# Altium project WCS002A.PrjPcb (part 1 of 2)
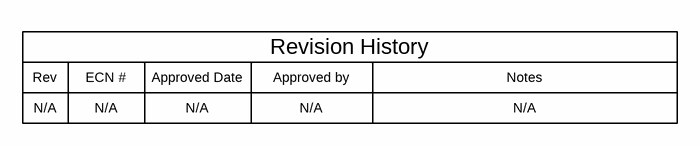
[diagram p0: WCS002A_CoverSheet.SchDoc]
CopyrightYear: 2015; PCB_Layout: Tessolve; PCB_Rev: A; PRJ_Customer: TI CONFIDENTIAL; PRJ_Engineer: Prajay Madhavan; PRJ_Number: WCS002; PRJ_Title: WCS002A; SCH_Rev: A; TechSupport: http://www.ti.com/support; TID: N/A
6 sheets, 312 parts. Net scope: global (net labels, ports and power ports of the same name join across sheets).
Board file: WCS002A.PcbDoc
Sheets:
  WCS002A_CoverSheet.SchDoc
  WCS002A_EmulationCircuit.SchDoc
  WCS002A_EngineArea.SchDoc
  WCS002A_EVM_Hardware.SchDoc
  WCS002A_HostInterface_ADC.SchDoc
  WCS002A_PowerLedsSwitchSensors.SchDoc

## Sheet WCS002A_CoverSheet.SchDoc: Cover Sheet
size 558 x 431 mm; Date: Not shown in title block; ApprovedBy: Not shown in title block; CheckedBy: Not shown in title block; Author: Not shown in title block; CompanyName: Not shown in title block; Engineer: Not shown in title block; Organization: Not shown in title block; Address1: Not shown in title block; Address2: Not shown in title block; Address3: Not shown in title block; Address4: Not shown in title block; DocumentNumber: 1; Revision: Use project parameter SCH_Rev; SheetNumber: 1; SheetTotal: 6; PageSetup: Record=PageOptions¦CenterHorizontal=True¦CenterVertical=True¦PrintScale=1.00¦XCorrection=1.00¦YCorrection=1.00¦PrintKind=0¦BorderSize=5000000¦LeftOffset=0¦BottomOffset=0¦Orientation=2¦PaperLength=1000¦PaperWidth=1000¦Scale=100¦PaperSource=15¦PrintQuality=600¦MediaType=1¦DitherType=10¦PaperKind=Letter¦PrintScaleMode=1

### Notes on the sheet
- Rev
- ECN #
- Approved Date
- Approved by
- Revision History
- Notes
- N/A

## Sheet WCS002A_EmulationCircuit.SchDoc: Emulation Circuit
size 558 x 431 mm; Date: Not shown in title block; ApprovedBy: Not shown in title block; CheckedBy: Not shown in title block; Author: Not shown in title block; CompanyName: Not shown in title block; Engineer: Not shown in title block; Organization: Not shown in title block; Address1: Not shown in title block; Address2: Not shown in title block; Address3: Not shown in title block; Address4: Not shown in title block; DocumentNumber: 4; Revision: Use project parameter SCH_Rev; SheetNumber: 4; SheetTotal: 6; PageSetup: Record=PageOptions¦CenterHorizontal=True¦CenterVertical=True¦PrintScale=1.00¦XCorrection=1.00¦YCorrection=1.00¦PrintKind=0¦BorderSize=5000000¦LeftOffset=0¦BottomOffset=0¦Orientation=2¦PaperLength=1000¦PaperWidth=1000¦Scale=100¦PaperSource=15¦PrintQuality=600¦MediaType=1¦DitherType=10¦PaperKind=Letter¦PrintScaleMode=1
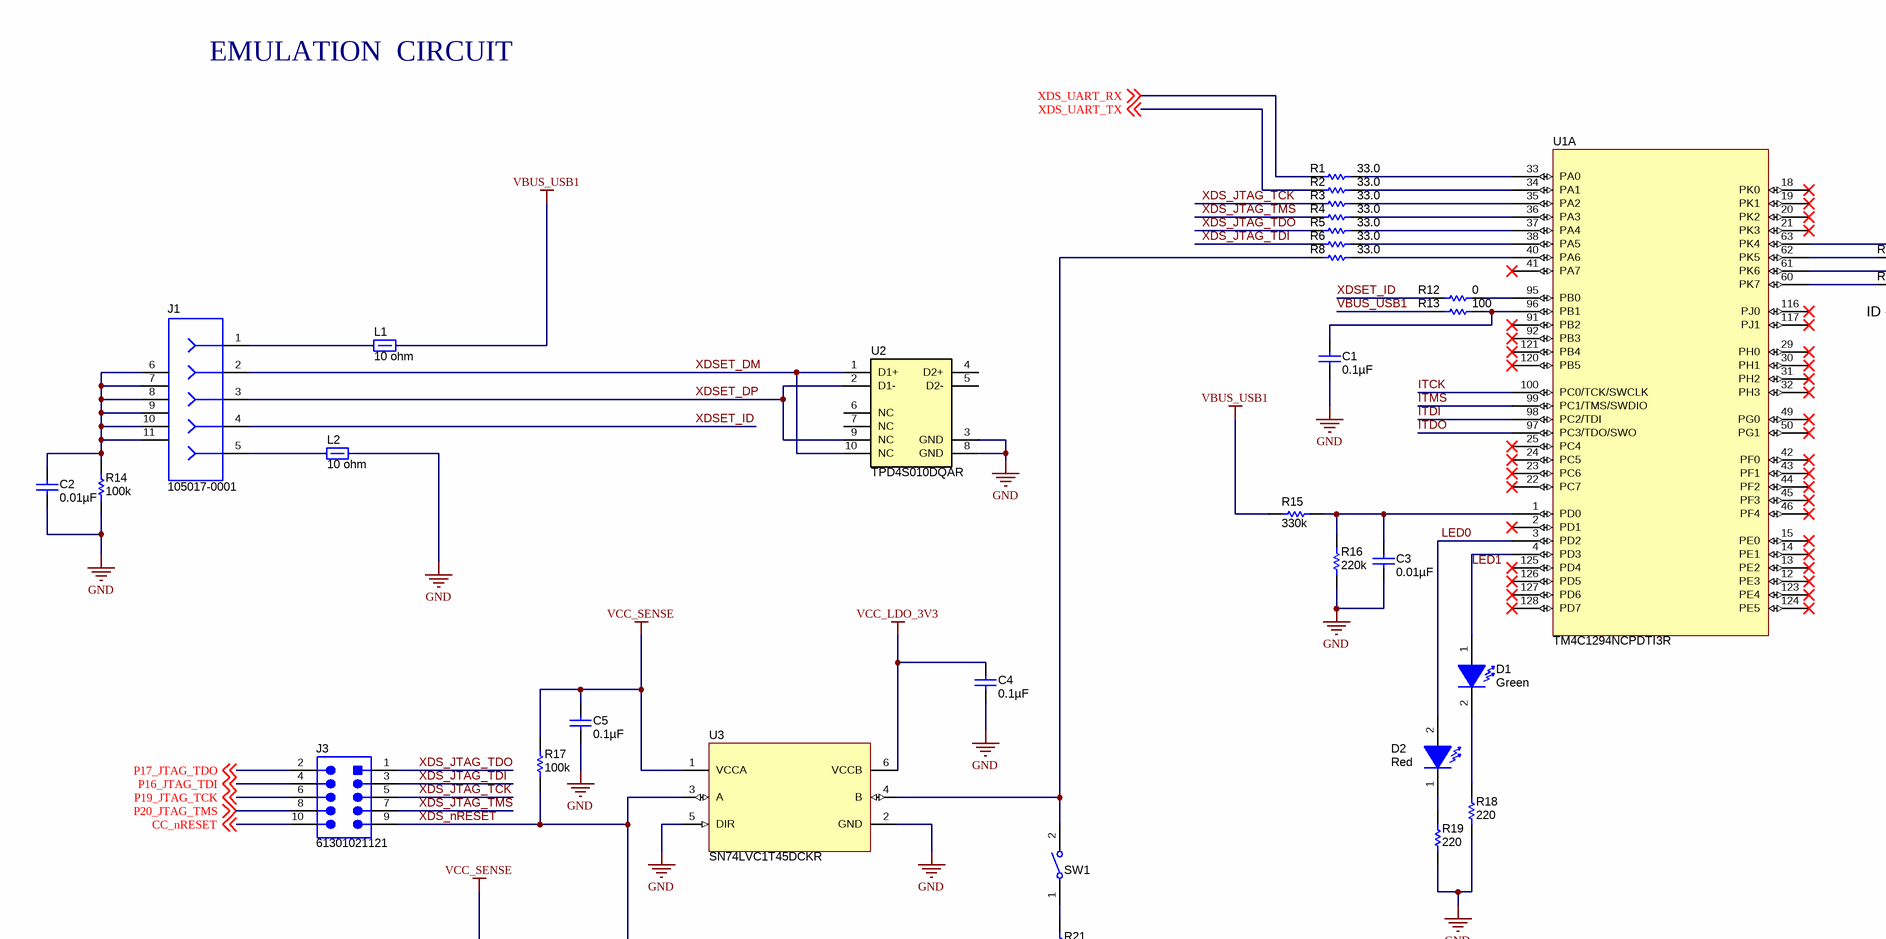
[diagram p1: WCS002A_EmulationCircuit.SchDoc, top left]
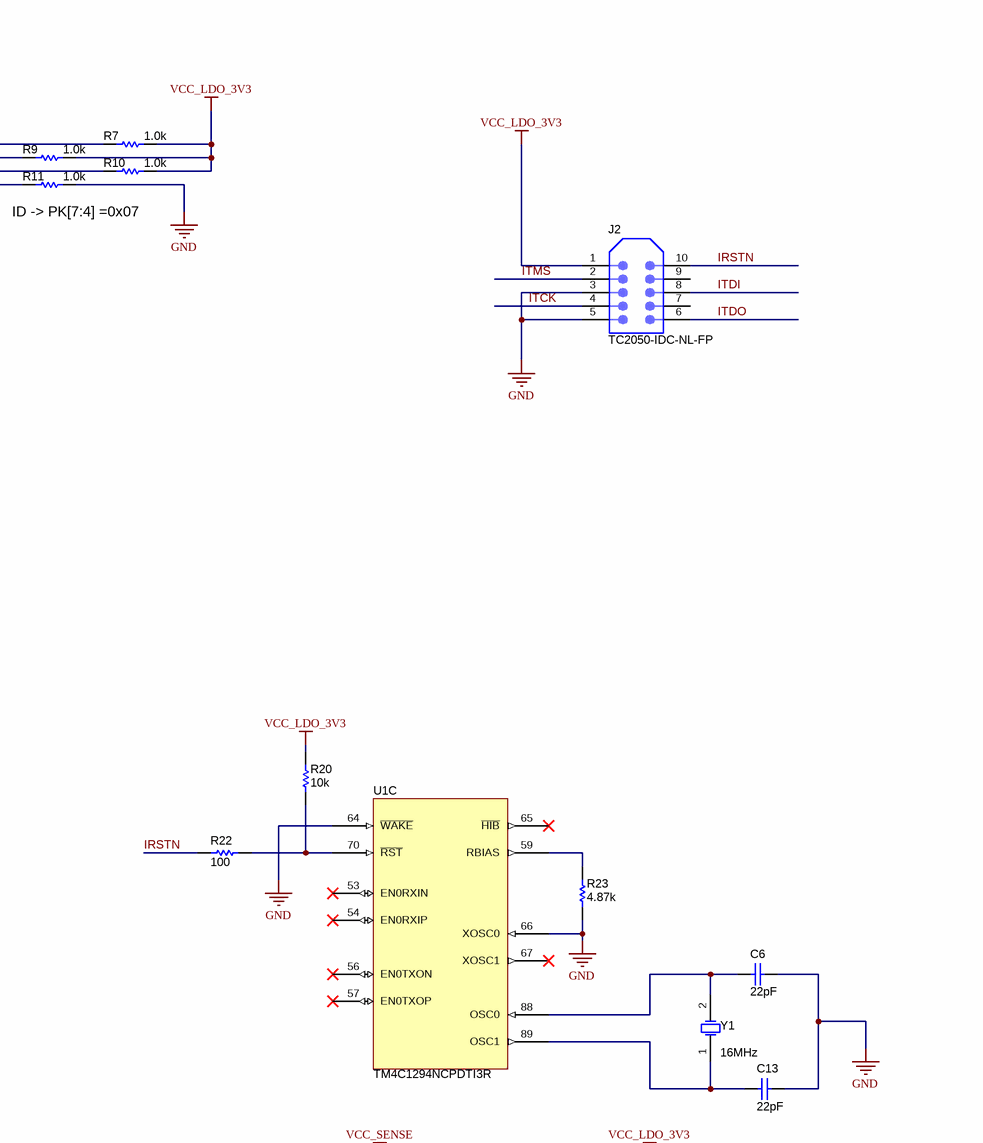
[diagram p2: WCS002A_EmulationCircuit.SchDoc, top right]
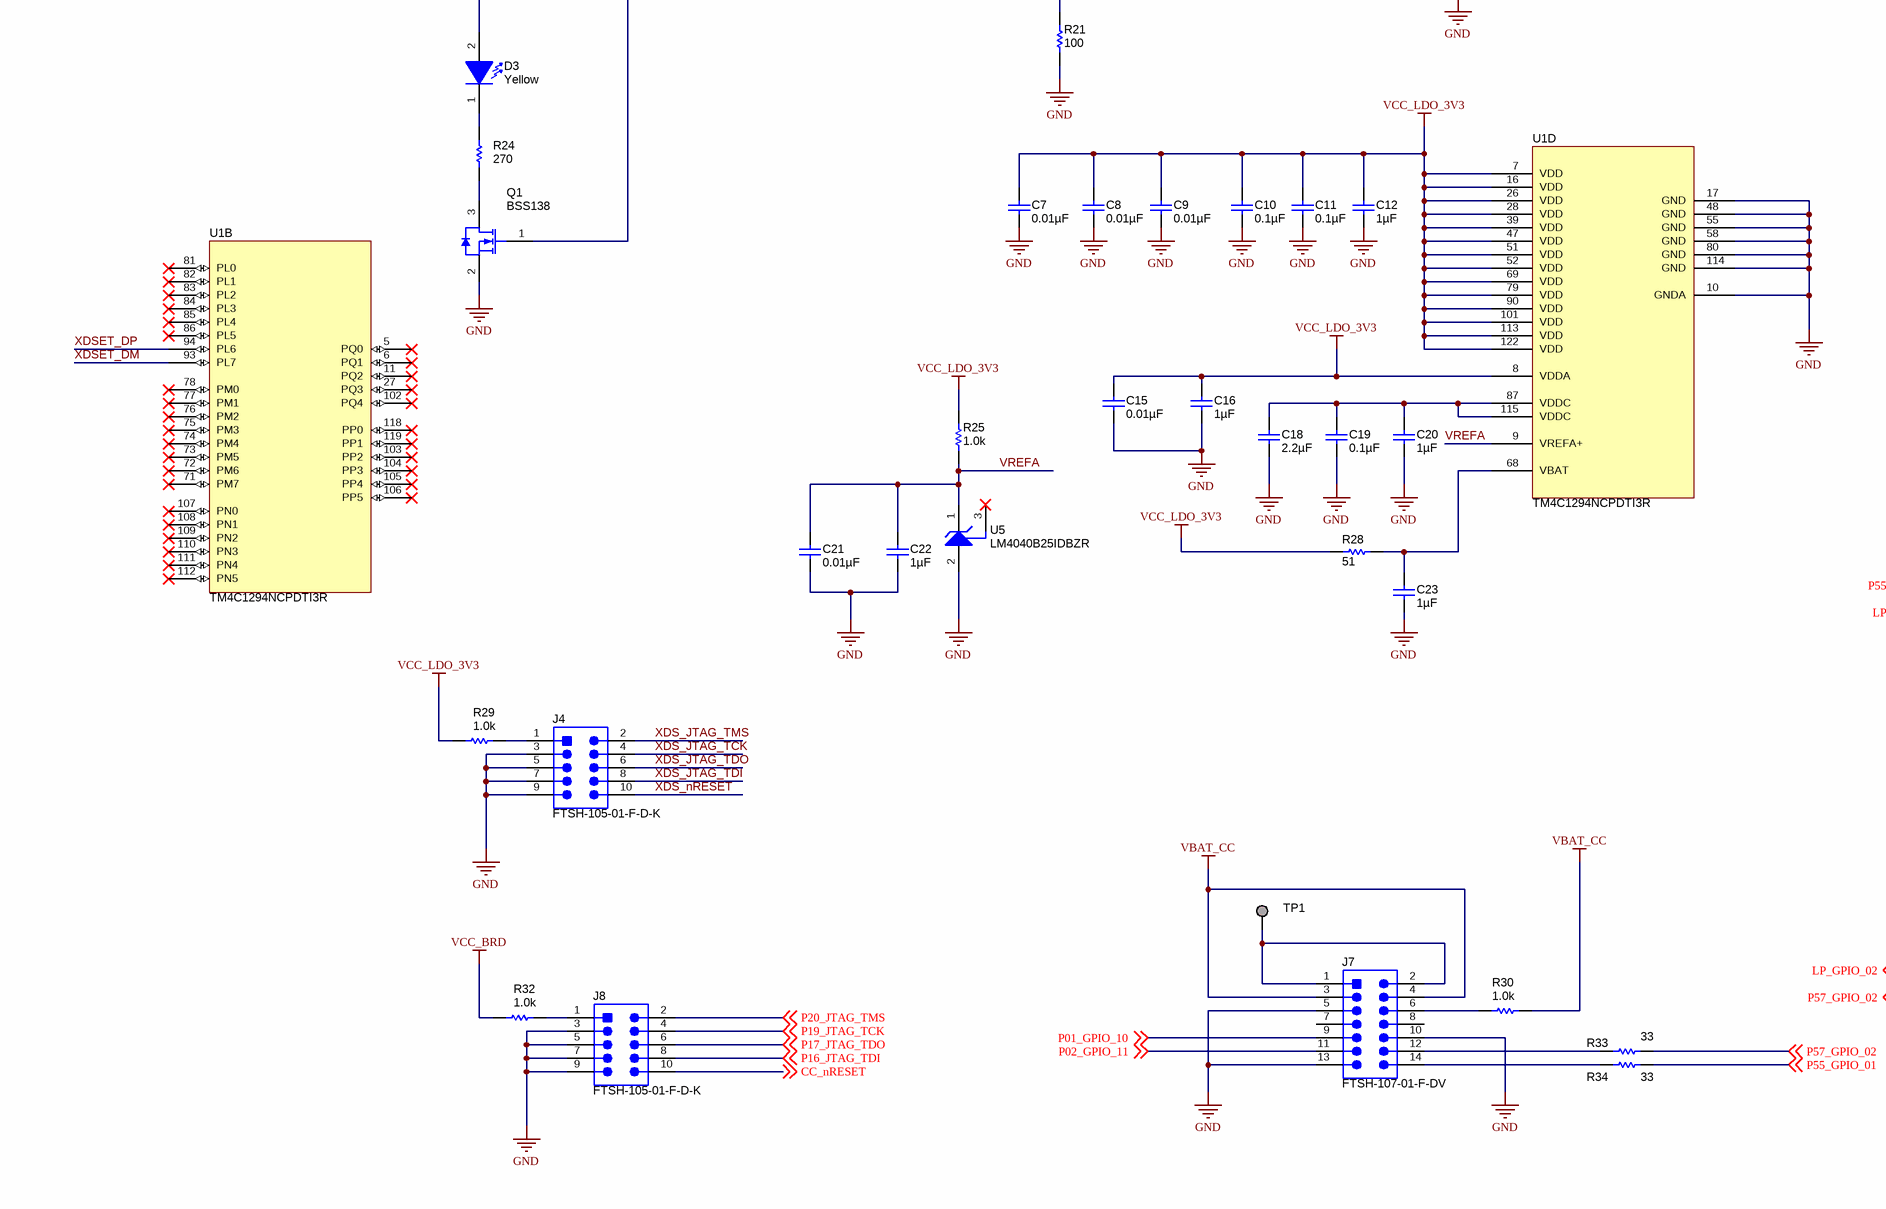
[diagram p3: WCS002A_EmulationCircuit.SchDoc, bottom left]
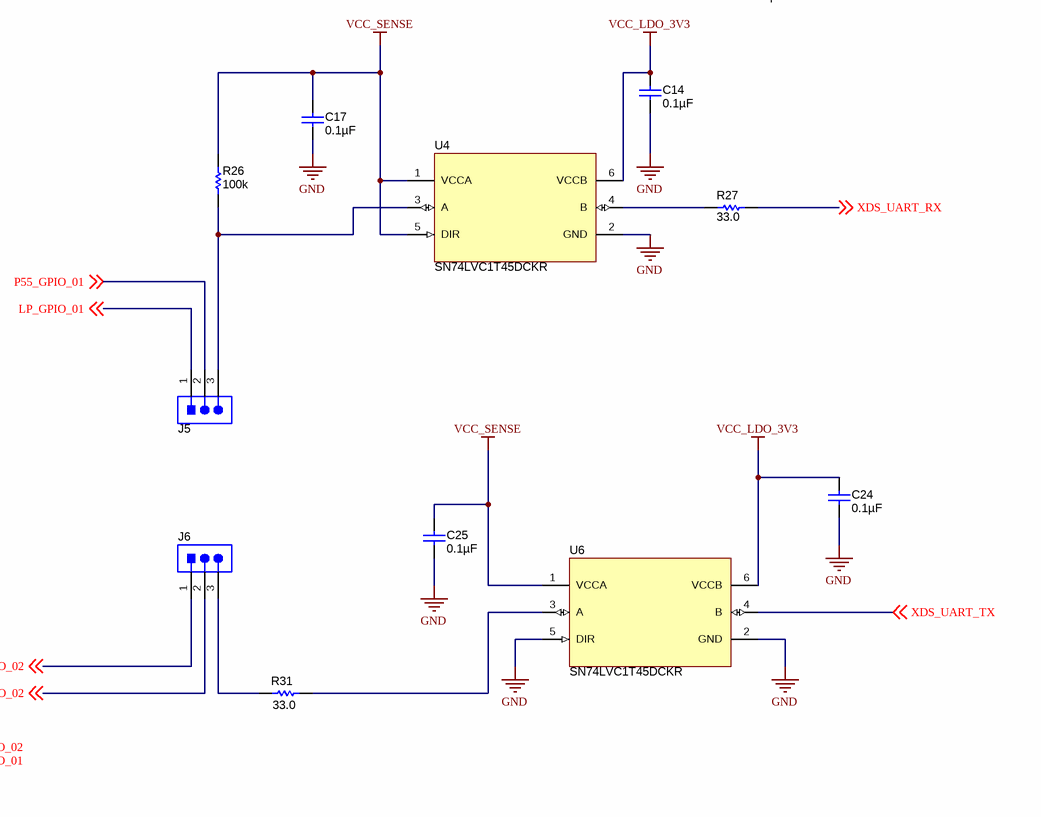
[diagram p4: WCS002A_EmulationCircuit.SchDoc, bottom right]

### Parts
C1  ValueDisplayed: 0.1µF  [0402]  (hidden comment: C1005X5R1A104K050BA)
C2  ValueDisplayed: 0.01µF  [0402]  (hidden comment: C1005X7R1C103K)
C3  ValueDisplayed: 0.01µF  [0402]  (hidden comment: C1005X7R1C103K)
C4  ValueDisplayed: 0.1µF  [0402]  (hidden comment: C1005X5R1A104K050BA)
C5  ValueDisplayed: 0.1µF  [0402]  (hidden comment: C1005X5R1A104K050BA)
C6  ValueDisplayed: 22pF  [0402]  (hidden comment: GRM1555C1H220FA01D)
C7  ValueDisplayed: 0.01µF  [0402]  (hidden comment: C1005X7R1C103K)
C8  ValueDisplayed: 0.01µF  [0402]  (hidden comment: C1005X7R1C103K)
C9  ValueDisplayed: 0.01µF  [0402]  (hidden comment: C1005X7R1C103K)
C10  ValueDisplayed: 0.1µF  [0603]  (hidden comment: 06033D104KAT2A)
C11  ValueDisplayed: 0.1µF  [0603]  (hidden comment: 06033D104KAT2A)
C12  ValueDisplayed: 1µF  [0402]  (hidden comment: C1005X5R1C105K050BC)
C13  ValueDisplayed: 22pF  [0402]  (hidden comment: GRM1555C1H220FA01D)
C14  ValueDisplayed: 0.1µF  [0402]  (hidden comment: C1005X5R1A104K050BA)
C15  ValueDisplayed: 0.01µF  [0402]  (hidden comment: C1005X7R1C103K)
C16  ValueDisplayed: 1µF  [0402]  (hidden comment: C1005X5R1C105K050BC)
C17  ValueDisplayed: 0.1µF  [0402]  (hidden comment: C1005X5R1A104K050BA)
C18  ValueDisplayed: 2.2µF  [0402]  (hidden comment: C1005X5R1C225K050BC)
C19  ValueDisplayed: 0.1µF  [0603]  (hidden comment: 06033D104KAT2A)
C20  ValueDisplayed: 1µF  [0402]  (hidden comment: C1005X5R1C105K050BC)
C21  ValueDisplayed: 0.01µF  [0402]  (hidden comment: C1005X7R1C103K)
C22  ValueDisplayed: 1µF  [0402]  (hidden comment: C1005X5R1C105K050BC)
C23  ValueDisplayed: 1µF  [0402]  (hidden comment: C1005X5R1C105K050BC)
C24  ValueDisplayed: 0.1µF  [0402]  (hidden comment: C1005X5R1A104K050BA)
C25  ValueDisplayed: 0.1µF  [0402]  (hidden comment: C1005X5R1A104K050BA)
D1  value Green  [LED_SML-LX0603GW]  (hidden comment: SML-LX0603GW-TR)
D2  value Red  [SML-31_Red]  (hidden comment: SML-311UTT86)
D3  value Yellow  [WL-SMCW_YELLOW]  (hidden comment: 150060YS75000)
J1  105017-0001  [CONN_105017-0001]
J2  TC2050-IDC-NL-FP  [Tag_TC2050-NL]  (no BOM)
J3  61301021121  [WURTH_61301021121]
J4  FTSH-105-01-F-D-K  [Samtec_FTSH-105-01-x-D-K]
J5  61300311121  [WURTH_61300311121]  (value not drawn)
J6  61300311121  [WURTH_61300311121]  (value not drawn)
J7  FTSH-107-01-F-DV  [Samtec_FTSH-107-01-x-DV]
J8  FTSH-105-01-F-D-K  [Samtec_FTSH-105-01-x-D-K]
L1  value 10 ohm  [0402]  (hidden comment: BLM15AG100SN1D)
L2  value 10 ohm  [0402]  (hidden comment: BLM15AG100SN1D)
Q1  BSS138  [SOT-23]
R1  ValueDisplayed: 33.0  [0402]  (hidden comment: ERJ-2RKF33R0X)
R2  ValueDisplayed: 33.0  [0402]  (hidden comment: ERJ-2RKF33R0X)
R3  ValueDisplayed: 33.0  [0402]  (hidden comment: ERJ-2RKF33R0X)
R4  ValueDisplayed: 33.0  [0402]  (hidden comment: ERJ-2RKF33R0X)
R5  ValueDisplayed: 33.0  [0402]  (hidden comment: ERJ-2RKF33R0X)
R6  ValueDisplayed: 33.0  [0402]  (hidden comment: ERJ-2RKF33R0X)
R7  ValueDisplayed: 1.0k  [0402]  (hidden comment: CRCW04021K00JNED)
R8  ValueDisplayed: 33.0  [0402]  (hidden comment: ERJ-2RKF33R0X)
R9  ValueDisplayed: 1.0k  [0402]  (hidden comment: CRCW04021K00JNED)
R10  ValueDisplayed: 1.0k  [0402]  (hidden comment: CRCW04021K00JNED)
R11  ValueDisplayed: 1.0k  [0402]  (hidden comment: CRCW04021K00JNED)
R12  ValueDisplayed: 0  [0402]  (hidden comment: ERJ-2GE0R00X)
R13  ValueDisplayed: 100  [0402]  (hidden comment: CRCW0402100RJNED)
R14  ValueDisplayed: 100k  [0603]  (hidden comment: CRCW0603100KJNEA)
R15  ValueDisplayed: 330k  [0402]  (hidden comment: CRCW0402330KJNED)
R16  ValueDisplayed: 220k  [0402]  (hidden comment: CRCW0402220KJNED)
R17  ValueDisplayed: 100k  [0402]  (hidden comment: CRCW0402100KJNED)
R18  ValueDisplayed: 220  [0603]  (hidden comment: CRCW0603220RJNEA)
R19  ValueDisplayed: 220  [0603]  (hidden comment: CRCW0603220RJNEA)
R20  ValueDisplayed: 10k  [0402]  (hidden comment: CRCW040210K0JNED)
R21  ValueDisplayed: 100  [0402]  (hidden comment: ERJ-2RKF1000X)
R22  ValueDisplayed: 100  [0402]  (hidden comment: CRCW0402100RFKED)
R23  ValueDisplayed: 4.87k  [0603]  (hidden comment: CRCW06034K87FKEA)
R24  ValueDisplayed: 270  [0603]  (hidden comment: CRCW0603270RJNEA)
R25  ValueDisplayed: 1.0k  [0402]  (hidden comment: CRCW04021K00JNED)
R26  ValueDisplayed: 100k  [0402]  (hidden comment: CRCW0402100KJNED)
R27  ValueDisplayed: 33.0  [0402]  (hidden comment: ERJ-2RKF33R0X)
R28  ValueDisplayed: 51  [0402]  (hidden comment: CRCW040251R0JNED)
R29  ValueDisplayed: 1.0k  [0402]  (hidden comment: CRCW04021K00JNED)
R30  ValueDisplayed: 1.0k  [0402]  (hidden comment: CRCW04021K00JNED)
R31  ValueDisplayed: 33.0  [0402]  (hidden comment: ERJ-2RKF33R0X)
R32  ValueDisplayed: 1.0k  [0402]  (hidden comment: CRCW04021K00JNED)
R33  ValueDisplayed: 33  [0603]  (hidden comment: CRCW060333R0JNEA)
R34  ValueDisplayed: 33  [0603]  (hidden comment: CRCW060333R0JNEA)
SW1  MJTP1117  [SW_MJTP1117]  (value not drawn)
TP1  TESTPOINT  [TESTPOINT]  (value not drawn)  (no BOM)
U1  TM4C1294NCPDTI3R  [PDT0128A_N]  (parts A,B,C,D of 4)
U2  TPD4S010DQAR  [DQA0010A]
U3  SN74LVC1T45DCKR  [DCK0006A_N]
U4  SN74LVC1T45DCKR  [DCK0006A_N]
U5  LM4040B25IDBZR  [DBZ0003A_N]
U6  SN74LVC1T45DCKR  [DCK0006A_N]
Y1  Frequency: 16MHz  [XTAL_ABM3]  (hidden comment: ABM3-16.000MHZ-D2Y-T)

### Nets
GND: C1.2 C2.2 C3.2 C4.2 C5.2 C6.1 C7.2 C8.2 C9.2 C10.2 C11.2 C12.2 C13.1 C14.2 C15.2 C16.2 C17.2 C18.2 C19.2 C20.2 C21.2 C22.2 C23.2 C24.2 C25.2 J2.3 J2.5 J4.3 J4.5 J4.7 J4.9 J7.5 J7.10 J7.13 J8.3 J8.5 J8.7 J8.9 L2.2 Q1.2(S) R11.1 R14.1 R16.1 R18.1 R19.1 R21.1 R23.1 U1.10(GNDA) U1.17(GND) U1.48(GND) U1.55(GND) U1.58(GND) U1.64(~{WAKE}) U1.66(XOSC0) U1.80(GND) U1.114(GND) U2.3(GND) U2.8(GND) U3.2(GND) U3.5(DIR) U4.2(GND) U5.2(ANODE) U6.2(GND) U6.5(DIR)
VBAT_CC: J7.3 J7.4 R30.2
VBUS_USB1: L1.2 R13.1 R15.1
VCC_BRD: R32.1
VCC_LDO_3V3: C4.1 C7.1 C8.1 C9.1 C10.1 C11.1 C12.1 C14.1 C15.1 C16.1 C24.1 J2.1 R7.1 R9.1 R10.1 R20.1 R25.2 R28.1 R29.1 U1.7(VDD) U1.8(VDDA) U1.16(VDD) U1.26(VDD) U1.28(VDD) U1.39(VDD) U1.47(VDD) U1.51(VDD) U1.52(VDD) U1.69(VDD) U1.79(VDD) U1.90(VDD) U1.101(VDD) U1.113(VDD) U1.122(VDD) U3.6(VCCB) U4.6(VCCB) U6.6(VCCB)
VCC_SENSE: C5.1 C17.1 C25.1 D3.2(A) R17.2 R26.1 U3.1(VCCA) U4.1(VCCA) U4.5(DIR) U6.1(VCCA)
CC_nRESET: J3.10 J8.10 ; off-sheet CC_nRESET
IRSTN: J2.10 R22.1
ITCK: J2.4 U1.100(PC0/TCK/SWCLK)
ITDI: J2.8 U1.98(PC2/TDI)
ITDO: J2.6 U1.97(PC3/TDO/SWO)
ITMS: J2.2 U1.99(PC1/TMS/SWDIO)
LED0: D2.2(A) U1.3(PD2)
LED1: D1.1(A) U1.4(PD3)
LP_GPIO_01: J5.1 ; off-sheet LP_GPIO_01
LP_GPIO_02: J6.1 ; off-sheet LP_GPIO_02
P01_GPIO_10: J7.9 ; off-sheet P01_GPIO_10
P02_GPIO_11: J7.11 ; off-sheet P02_GPIO_11
P16_JTAG_TDI: J3.4 J8.8 ; off-sheet P16_JTAG_TDI
P17_JTAG_TDO: J3.2 J8.6 ; off-sheet P17_JTAG_TDO
P19_JTAG_TCK: J3.6 J8.4 ; off-sheet P19_JTAG_TCK
P20_JTAG_TMS: J3.8 J8.2 ; off-sheet P20_JTAG_TMS
P55_GPIO_01: J5.2 R34.1 ; off-sheet P55_GPIO_01
P57_GPIO_02: J6.2 R33.1 ; off-sheet P57_GPIO_02
VREFA: C21.1 C22.1 R25.1 U1.9(VREFA+) U5.1(CATHODE)
XDS_JTAG_TCK: J3.5 J4.4 R3.1
XDS_JTAG_TDI: J3.3 J4.8 R6.1
XDS_JTAG_TDO: J3.1 J4.6 R5.1
XDS_JTAG_TMS: J3.7 J4.2 R4.1
XDS_nRESET: J3.9 J4.10 Q1.1(G) R17.1 U3.3(A)
XDS_UART_RX: R1.1 R27.2 ; off-sheet XDS_UART_RX
XDS_UART_TX: R2.1 U6.4(B) ; off-sheet XDS_UART_TX
XDSET_DM: J1.2 U1.93(PL7) U2.1(D1+) U2.10(NC)
XDSET_DP: J1.3 U1.94(PL6) U2.2(D1-) U2.9(NC)
XDSET_ID: J1.4 R12.1
NetC1_1: C1.1 R13.2 U1.96(PB1)
NetC2_1: C2.1 J1.6 J1.7 J1.8 J1.9 J1.10 J1.11 R14.2
NetC3_1: C3.1 R15.2 R16.2 U1.1(PD0)
NetC6_2: C6.2 U1.88(OSC0) Y1.2(OSC2)
NetC13_2: C13.2 U1.89(OSC1) Y1.1(OSC1)
NetC18_1: C18.1 C19.1 C20.1 U1.87(VDDC) U1.115(VDDC)
NetC23_1: C23.1 R28.2 U1.68(VBAT)
NetD1_2: D1.2(K) R18.2
NetD2_1: D2.1(K) R19.2
NetD3_1: D3.1(K) R24.2
NetJ1_1: J1.1 L1.1
NetJ1_5: J1.5 L2.1
NetJ4_1: J4.1 R29.2
NetJ5_3: J5.3 R26.2 U4.3(A)
NetJ6_3: J6.3 R31.1
NetJ7_1: J7.1 J7.2 TP1.1
NetJ7_6: J7.6 R30.1
NetJ7_12: J7.12 R33.2
NetJ7_14: J7.14 R34.2
NetJ8_1: J8.1 R32.2
NetQ1_3: Q1.3(D) R24.1
NetR1_2: R1.2 U1.33(PA0)
NetR2_2: R2.2 U1.34(PA1)
NetR3_2: R3.2 U1.35(PA2)
NetR4_2: R4.2 U1.36(PA3)
NetR5_2: R5.2 U1.37(PA4)
NetR6_2: R6.2 U1.38(PA5)
NetR7_2: R7.2 U1.63(PK4)
NetR8_1: R8.1 SW1.2 U3.4(B)
NetR8_2: R8.2 U1.40(PA6)
NetR9_2: R9.2 U1.62(PK5)
NetR10_2: R10.2 U1.61(PK6)
NetR11_2: R11.2 U1.60(PK7)
NetR12_2: R12.2 U1.95(PB0)
NetR20_2: R20.2 R22.2 U1.70(~{RST})
NetR21_2: R21.2 SW1.1
NetR23_2: R23.2 U1.59(RBIAS)
NetR27_1: R27.1 U4.4(B)
NetR31_2: R31.2 U6.3(A)

Not connected (* = marked no-connect by the designer): J2 7 9; J7 7 8; U1 2(PD1)* 5(PQ0)* 6(PQ1)* 11(PQ2)* 12(PE3)* 13(PE2)* 14(PE1)* 15(PE0)* 18(PK0)* 19(PK1)* 20(PK2)* 21(PK3)* 22(PC7)* 23(PC6)* 24(PC5)* 25(PC4)* 27(PQ3)* 29(PH0)* 30(PH1)* 31(PH2)* 32(PH3)* 41(PA7)* 42(PF0)* 43(PF1)* 44(PF2)* 45(PF3)* 46(PF4)* 49(PG0)* 50(PG1)* 53(EN0RXIN)* 54(EN0RXIP)* 56(EN0TXON)* 57(EN0TXOP)* 65(~{HIB})* 67(XOSC1)* 71(PM7)* 72(PM6)* 73(PM5)* 74(PM4)* 75(PM3)* 76(PM2)* 77(PM1)* 78(PM0)* 81(PL0)* 82(PL1)* 83(PL2)* 84(PL3)* 85(PL4)* 86(PL5)* 91(PB2)* 92(PB3)* 102(PQ4)* 103(PP2)* 104(PP3)* 105(PP4)* 106(PP5)* 107(PN0)* 108(PN1)* 109(PN2)* 110(PN3)* 111(PN4)* 112(PN5)* 116(PJ0)* 117(PJ1)* 118(PP0)* 119(PP1)* 120(PB5)* 121(PB4)* 123(PE4)* 124(PE5)* 125(PD4)* 126(PD5)* 127(PD6)* 128(PD7)*; U2 4(D2+) 5(D2-) 6(NC) 7(NC); U5 3(NC)*

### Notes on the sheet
- EMULATION  CIRCUIT
- ID -> PK[7:4] =0x07

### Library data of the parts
C1 C4 C5 C14 C17 C24 C25 = C1005X5R1A104K050BA: CAP, CERM, 0.1 µF, 10 V, +/- 10%, X5R, 0402; Manufacturer: TDK; Polarized: N; CompType: Capacitor; Value: 0.1uF; U/M: EA; Cap_F: 0.0000001; Tolerance_%: 10; Value1: Unknown; Value2: 10V; TaMin_C: -55; TaMax_C: 85
C2 C3 C7-C9 C15 C21 = C1005X7R1C103K: CAP, CERM, 0.01 µF, 16 V, +/- 10%, X7R, 0402; Manufacturer: TDK; Polarized: N; CompType: Capacitor; Value: 0.01uF; U/M: EA; Cap_F: 0.00000001; Tolerance_%: 10; ESR_ohm: 0.0623; Value1: 0.0623 ohm; VDC_V: 16; Value2: 16V; TaMin_C: -55; TaMax_C: 125; AEC Category: Q200
C6 C13 = GRM1555C1H220FA01D: CAP, CERM, 22 pF, 50 V, +/- 1%, C0G/NP0, 0402; Manufacturer: MuRata; Polarized: N; CompType: Capacitor; Value: 22pF; U/M: EA; Cap_F: 0.000000000022; Tolerance_%: 1; Value1: Unknown; VDC_V: 50; Value2: 50V; TaMin_C: -55; TaMax_C: 125; AEC Category: Q200
C10 C11 C19 = 06033D104KAT2A: CAP, CERM, 0.1 µF, 25 V, +/- 10%, X5R, 0603; Manufacturer: AVX; Polarized: N; CompType: Capacitor; Value: 0.1uF; U/M: EA; Cap_F: 0.0000001; Tolerance_%: 10; ESR_ohm: 0.048; Value1: 0.048 ohm; VDC_V: 25; Value2: 25V; IRMS_A: 0.53; TaMin_C: -55; TaMax_C: 85; AEC Category: Q200
C12 C16 C20 C22 C23 = C1005X5R1C105K050BC: CAP, CERM, 1 µF, 16 V, +/- 10%, X5R, 0402; Manufacturer: TDK; Polarized: N; CompType: Capacitor; Value: 1uF; U/M: EA; Cap_F: 0.000001; Tolerance_%: 10; Value1: Unknown; VDC_V: 16; Value2: 16V; TaMin_C: -55; TaMax_C: 85; AEC Category: Q200
C18 = C1005X5R1C225K050BC: CAP, CERM, 2.2 µF, 16 V, +/- 10%, X5R, 0402; Manufacturer: TDK; Polarized: N; CompType: Capacitor; Value: 2.2uF; U/M: EA; Cap_F: 0.0000022; Tolerance_%: 10; Value1: Unknown; VDC_V: 16; Value2: 16V; TaMin_C: -55; TaMax_C: 85; AEC Category: Q200
D1 = SML-LX0603GW-TR: LED, Green, SMD; Manufacturer: Lumex; Vf_V: 2.2; Value2: 2.2V; Io_A: 0.02; Tjmax_C: 85; Value1: W; U/M: EA
D2 = SML-311UTT86: LED, Red, SMD; Manufacturer: Rohm; Type: AlInGaP; Vf_V: 1.8; Value2: 1.8V; Io_A: 0.002; Value1: W; U/M: EA
D3 = 150060YS75000: LED, Yellow, SMD; Manufacturer: Wurth Elektronik eiSos; Type: AlInGaP; Vf_V: 2; Value2: 2V; Io_A: 0.02; Value1: W; U/M: EA
J1 = 105017-0001: Connector, Receptacle, Micro-USB Type B, R/A, Bottom Mount SMT; Manufacturer: Molex; SymbolCreator: a0412235; U/M: EA
J2 = TC2050-IDC-NL-FP: Footprint for Tag-Connect TC2050 No-Legs cables; SymbolCreator: Altium; CompType: Receptacle; U/M: EA; Note: Footprint only, to mate with Tag-Connect TC2050 No-Legs cables
J3 = 61301021121: Header, 2.54 mm, 5x2, Gold, TH; Manufacturer: Wurth Elektronik; SymbolCreator: a0412235; U/M: EA
J4 J8 = FTSH-105-01-F-D-K: Header, 1.27 mm, 5x2, Gold, TH; Manufacturer: Samtec; SymbolCreator: a0412235; U/M: EA
J5 J6 = 61300311121: Header, 2.54 mm, 3x1, Gold, TH; Manufacturer: Wurth Elektronik; SymbolCreator: a0799628; U/M: EA
J7 = FTSH-107-01-F-DV: Header, 1.27mm, 7x2, Gold, SMT; Manufacturer: Samtec; SymbolCreator: a0412235; Pitch_mm: 1.27; Gender: Male; Shrouded: N; Row_Count: 2; Current_A: 3.3; Cert_UL: Y
L1 L2 = BLM15AG100SN1D: Ferrite Bead, 10 ohm @ 100 MHz, 1 A, 0402; Manufacturer: MuRata; Imax_A: 1; DCR_ohm: 0.025; Value1: 0.025 ohm; Value2: 1A; ZTyp@100MHz_Ohm: 10
Q1 = BSS138: MOSFET, N-CH, 50 V, 0.22 A, SOT-23; Manufacturer: Fairchild Semiconductor; Alternate Manufacturer: None; U/M: EA; ChType: N; Value: 50V; VdsMax_V: 50; Value1: 6 ohm; Rdson45_ohm: 6; Value2: 1.7 nC; QgTyp_nC: 1.7; Vgs_V: 20; IdsMax_A: 0.22
R1-R6 R8 = ERJ-2RKF33R0X: RES, 33.0, 1%, 0.1 W, 0402; Manufacturer: Panasonic; CompType: Resistor; Value: 33.0; Res_ohm: 33; Value_Code: 33R0; Tolerance_%: 1; Power_W: 0.1; Value2: 0.1W; VDC_V: 50; TempCo: 100 ppm/C; U/M: EA; AEC Category: Q200
R7 R9-R11 R25 R29 R30 R32 = CRCW04021K00JNED: RES, 1.0 k, 5%, 0.063 W, 0402; Manufacturer: Vishay-Dale; CompType: Resistor; Value: 1.0k; Res_ohm: 1000; Value_Code: 1k00; Tolerance_%: 5; Power_W: 0.063; Value2: 0.063W; VDC_V: 50; TempCo: 200 ppm/C; EIA_Code: E24; U/M: EA
R12 = ERJ-2GE0R00X: RES, 0, 5%, 0.063 W, 0402; Manufacturer: Panasonic; CompType: Resistor; Value: 0; Value_Code: 0000; Tolerance_%: 5; Power_W: 0.063; Value2: 0.063W; VDC_V: 50; TempCo: 600 ppm/C; EIA_Code: E24; U/M: EA
R13 = CRCW0402100RJNED: RES, 100, 5%, 0.063 W, 0402; Manufacturer: Vishay-Dale; CompType: Resistor; Value: 100; Value_Code: 100R; Tolerance_%: 5; Power_W: 0.063; Value2: 0.063W; VDC_V: 50; TempCo: 200 ppm/C; EIA_Code: E24; U/M: EA; AEC Category: Q200
R14 = CRCW0603100KJNEA: RES, 100 k, 5%, 0.1 W, 0603; Manufacturer: Vishay-Dale; CompType: Resistor; Value: 100k; Res_ohm: 100000; Tolerance_%: 5; Power_W: 0.1; Value2: 0.1W; VDC_V: 75; TempCo: 200 ppm/C; EIA_Code: E24; U/M: EA; AEC Category: Q200
R15 = CRCW0402330KJNED: RES, 330 k, 5%, 0.063 W, 0402; Manufacturer: Vishay-Dale; CompType: Resistor; Value: 330k; Res_ohm: 330000; Tolerance_%: 5; Power_W: 0.063; Value2: 0.063W; VDC_V: 50; TempCo: 200 ppm/C; EIA_Code: E24; U/M: EA; AEC Category: Q200
R16 = CRCW0402220KJNED: RES, 220 k, 5%, 0.063 W, 0402; Manufacturer: Vishay-Dale; CompType: Resistor; Value: 220k; Res_ohm: 220000; Tolerance_%: 5; Power_W: 0.063; Value2: 0.063W; VDC_V: 50; TempCo: 200 ppm/C; EIA_Code: E24; U/M: EA; AEC Category: Q200
R17 R26 = CRCW0402100KJNED: RES, 100 k, 5%, 0.063 W, 0402; Manufacturer: Vishay-Dale; CompType: Resistor; Value: 100k; Res_ohm: 100000; Tolerance_%: 5; Power_W: 0.063; Value2: 0.063W; VDC_V: 50; TempCo: 200 ppm/C; EIA_Code: E24; U/M: EA
R18 R19 = CRCW0603220RJNEA: RES, 220, 5%, 0.1 W, 0603; Manufacturer: Vishay-Dale; CompType: Resistor; Value: 220; Value_Code: 220R; Tolerance_%: 5; Power_W: 0.1; Value2: 0.1W; VDC_V: 75; TempCo: 200 ppm/C; EIA_Code: E24; U/M: EA; AEC Category: Q200
R20 = CRCW040210K0JNED: RES, 10 k, 5%, 0.063 W, 0402; Manufacturer: Vishay-Dale; CompType: Resistor; Value: 10k; Res_ohm: 10000; Value_Code: 10k0; Tolerance_%: 5; Power_W: 0.063; Value2: 0.063W; VDC_V: 50; TempCo: 200 ppm/C; EIA_Code: E24; U/M: EA
R21 = ERJ-2RKF1000X: RES, 100, 1%, 0.1 W, 0402; Manufacturer: Panasonic; CompType: Resistor; Value: 100; Value_Code: 100R; Tolerance_%: 1; Power_W: 0.1; Value2: 0.1W; VDC_V: 50; TempCo: 100 ppm/C; EIA_Code: E96; U/M: EA
R22 = CRCW0402100RFKED: RES, 100, 1%, 0.063 W, 0402; Manufacturer: Vishay-Dale; CompType: Resistor; Value: 100; Value_Code: 100R; Tolerance_%: 1; Power_W: 0.063; Value2: 0.063W; VDC_V: 50; TempCo: 100 ppm/C; EIA_Code: E96; U/M: EA; AEC Category: Q200
R23 = CRCW06034K87FKEA: RES, 4.87 k, 1%, 0.1 W, 0603; Manufacturer: Vishay-Dale; CompType: Resistor; Value: 4.87k; Res_ohm: 4870; Value_Code: 4k87; Tolerance_%: 1; Power_W: 0.1; Value2: 0.1W; VDC_V: 75; TempCo: 100 ppm/C; EIA_Code: E96; U/M: EA; AEC Category: Q200
R24 = CRCW0603270RJNEA: RES, 270, 5%, 0.1 W, 0603; Manufacturer: Vishay-Dale; CompType: Resistor; Value: 270; Value_Code: 270R; Tolerance_%: 5; Power_W: 0.1; Value2: 0.1W; VDC_V: 75; TempCo: 200 ppm/C; EIA_Code: E24; U/M: EA
R27 R31 = ERJ-2RKF33R0X: RES, 33.0, 1%, 0.1 W, 0402; Manufacturer: Panasonic; CompType: Resistor; Value: 33.0; Res_ohm: 33; Value_Code: 33R0; Tolerance_%: 1; Power_W: 0.1; Value2: 0.1W; VDC_V: 50; TempCo: 100 ppm/C; U/M: EA
R28 = CRCW040251R0JNED: RES, 51, 5%, 0.063 W, 0402; Manufacturer: Vishay-Dale; CompType: Resistor; Value: 51; Value_Code: 51R0; Tolerance_%: 5; Power_W: 0.063; Value2: 0.063W; VDC_V: 50; TempCo: 200 ppm/C; EIA_Code: E24; U/M: EA; AEC Category: Q200
R33 R34 = CRCW060333R0JNEA: RES, 33, 5%, 0.1 W, 0603; Manufacturer: Vishay-Dale; CompType: Resistor; Value: 33; Value_Code: 33R0; Tolerance_%: 5; Power_W: 0.1; Value2: 0.1W; VDC_V: 75; TempCo: 200 ppm/C; EIA_Code: E24; U/M: EA
SW1 = MJTP1117: Switch, SPST-NO, Off-Mom, 1 Pos, 0.05A, 12VDC, TH; Manufacturer: APEM; SymbolCreator: a0799628; VDC_V: 12; PositionCount: 1; CurrentRating_mA: 50
TP1 = TESTPOINT: TEST POINT.  No entry in BOM.
U1 = TM4C1294NCPDTI3R: Tiva C Series Microcontroller, PDT0128A; Manufacturer: Texas Instruments; SymbolCreator: a0411947; CompType: IC; U/M: EA
U2 = TPD4S010DQAR: ESD Solution for High-Speed Differential Interface, 4 Channels, -40 to +85 degC,10-pin SON (DQA), Green (RoHS & no Sb/Br); Manufacturer: Texas Instruments; Alternate PartNumber: Equivalent; 1394 / Firewire: TRUE; Breakdown Voltage(Min)(V): 9; Differential Capacitance(pF): 0.05; IEC 61000-4-2 Contact(+/- kV): 8; IO Capacitance(Typ)(pF): 0.8; IO Leakage Current(nA): 10
U3 U4 U6 = SN74LVC1T45DCKR: Single-Bit Dual-Supply Bus Transceiver With Configurable Voltage Translation and 3-State Outputs, DCK0006A; Alternate PartNumber: SN74LVC1T45DCKT; Manufacturer: Texas Instruments; SymbolCreator: Altium; CompType: IC; U/M: EA
U5 = LM4040B25IDBZR: Precision Micropower Shunt Voltage Reference, 0.2% accuracy, 2.5 V, 15 ppm / degC, 15 mA, -40 to 85 degC, 3-pin SOT-23 (DBZ), Green (RoHS & no Sb/Br); Manufacturer: Texas Instruments; Alternate PartNumber: Equivalent; Initial Accuracy @ 25/deg C(%): 0.2; Iout/Iz(Max)(mA): 15; Min Iz for Regulation(uA): 75; Rating: Catalog; Temp Coeff(Max)(ppm/ degree C): 100; VO(V): 2.5
Y1 = ABM3-16.000MHZ-D2Y-T: Crystal, 16 MHz, 18 pF, SMD; Manufacturer: Abracon Corportation; SymbolCreator: a0412235; U/M: EA; TaMin_C: -40; TaMax_C: 85; Frequency Stability: ±30ppm

## Sheet WCS002A_EngineArea.SchDoc: Engineer Area
size 558 x 431 mm; Date: Not shown in title block; ApprovedBy: Not shown in title block; CheckedBy: Not shown in title block; Author: Not shown in title block; CompanyName: Not shown in title block; Engineer: Not shown in title block; Organization: Not shown in title block; Address1: Not shown in title block; Address2: Not shown in title block; Address3: Not shown in title block; Address4: Not shown in title block; DocumentNumber: 2; Revision: Use project parameter SCH_Rev; SheetNumber: 2; SheetTotal: 6; PageSetup: Record=PageOptions¦CenterHorizontal=True¦CenterVertical=True¦PrintScale=1.00¦XCorrection=1.00¦YCorrection=1.00¦PrintKind=0¦BorderSize=5000000¦LeftOffset=0¦BottomOffset=0¦Orientation=2¦PaperLength=1000¦PaperWidth=1000¦Scale=100¦PaperSource=15¦PrintQuality=600¦MediaType=1¦DitherType=10¦PaperKind=Letter¦PrintScaleMode=1
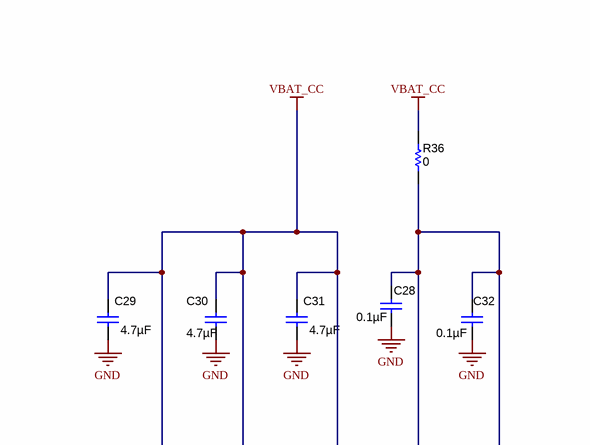
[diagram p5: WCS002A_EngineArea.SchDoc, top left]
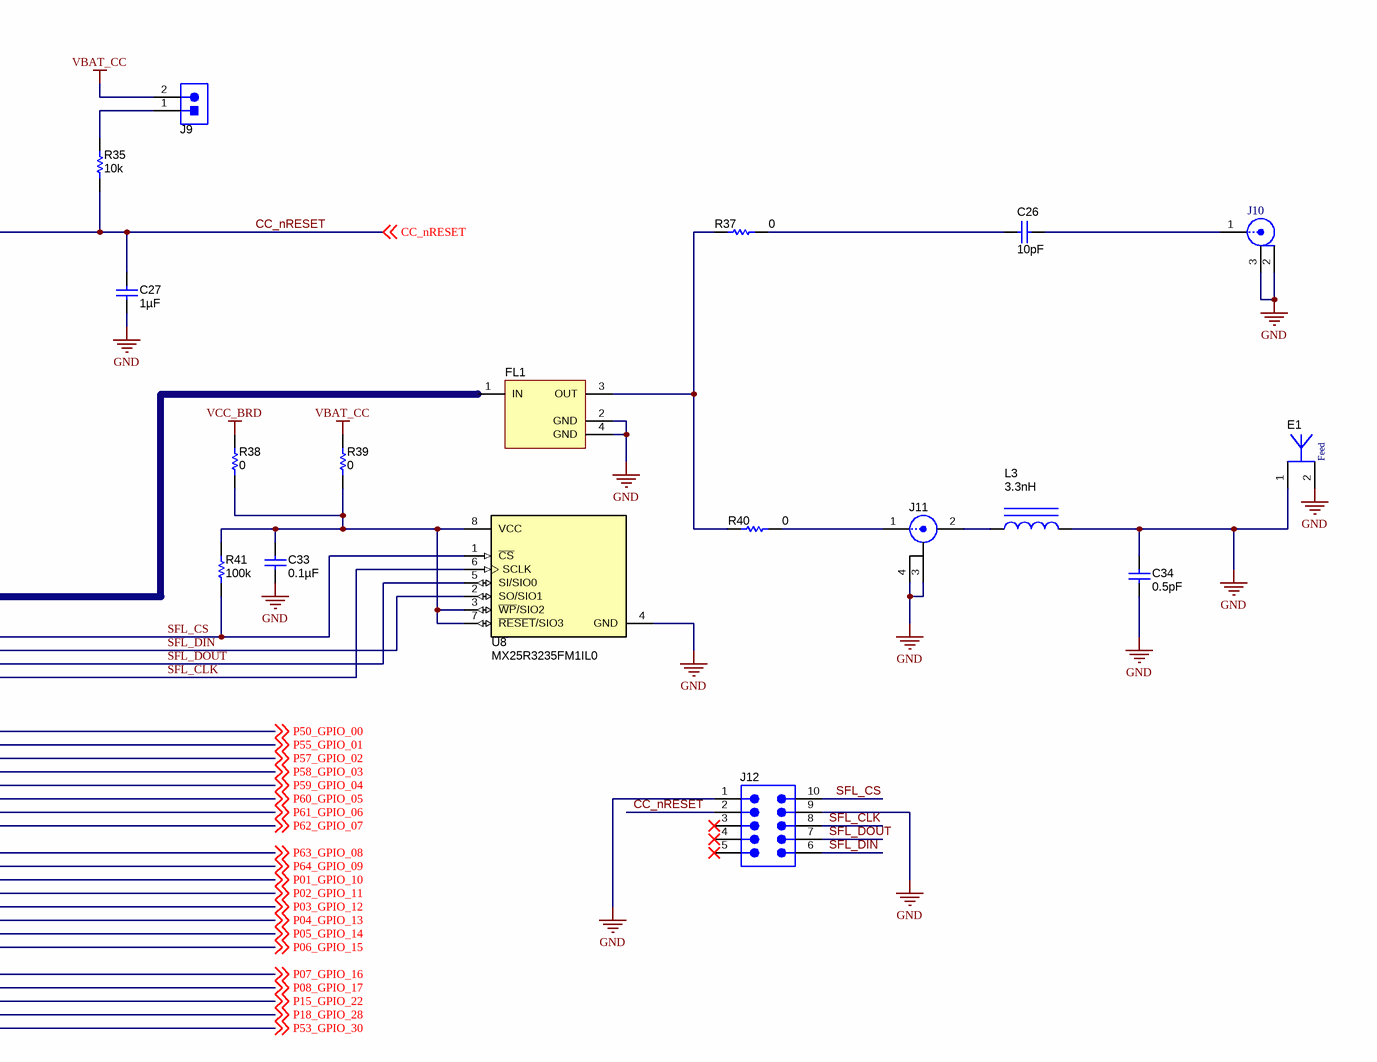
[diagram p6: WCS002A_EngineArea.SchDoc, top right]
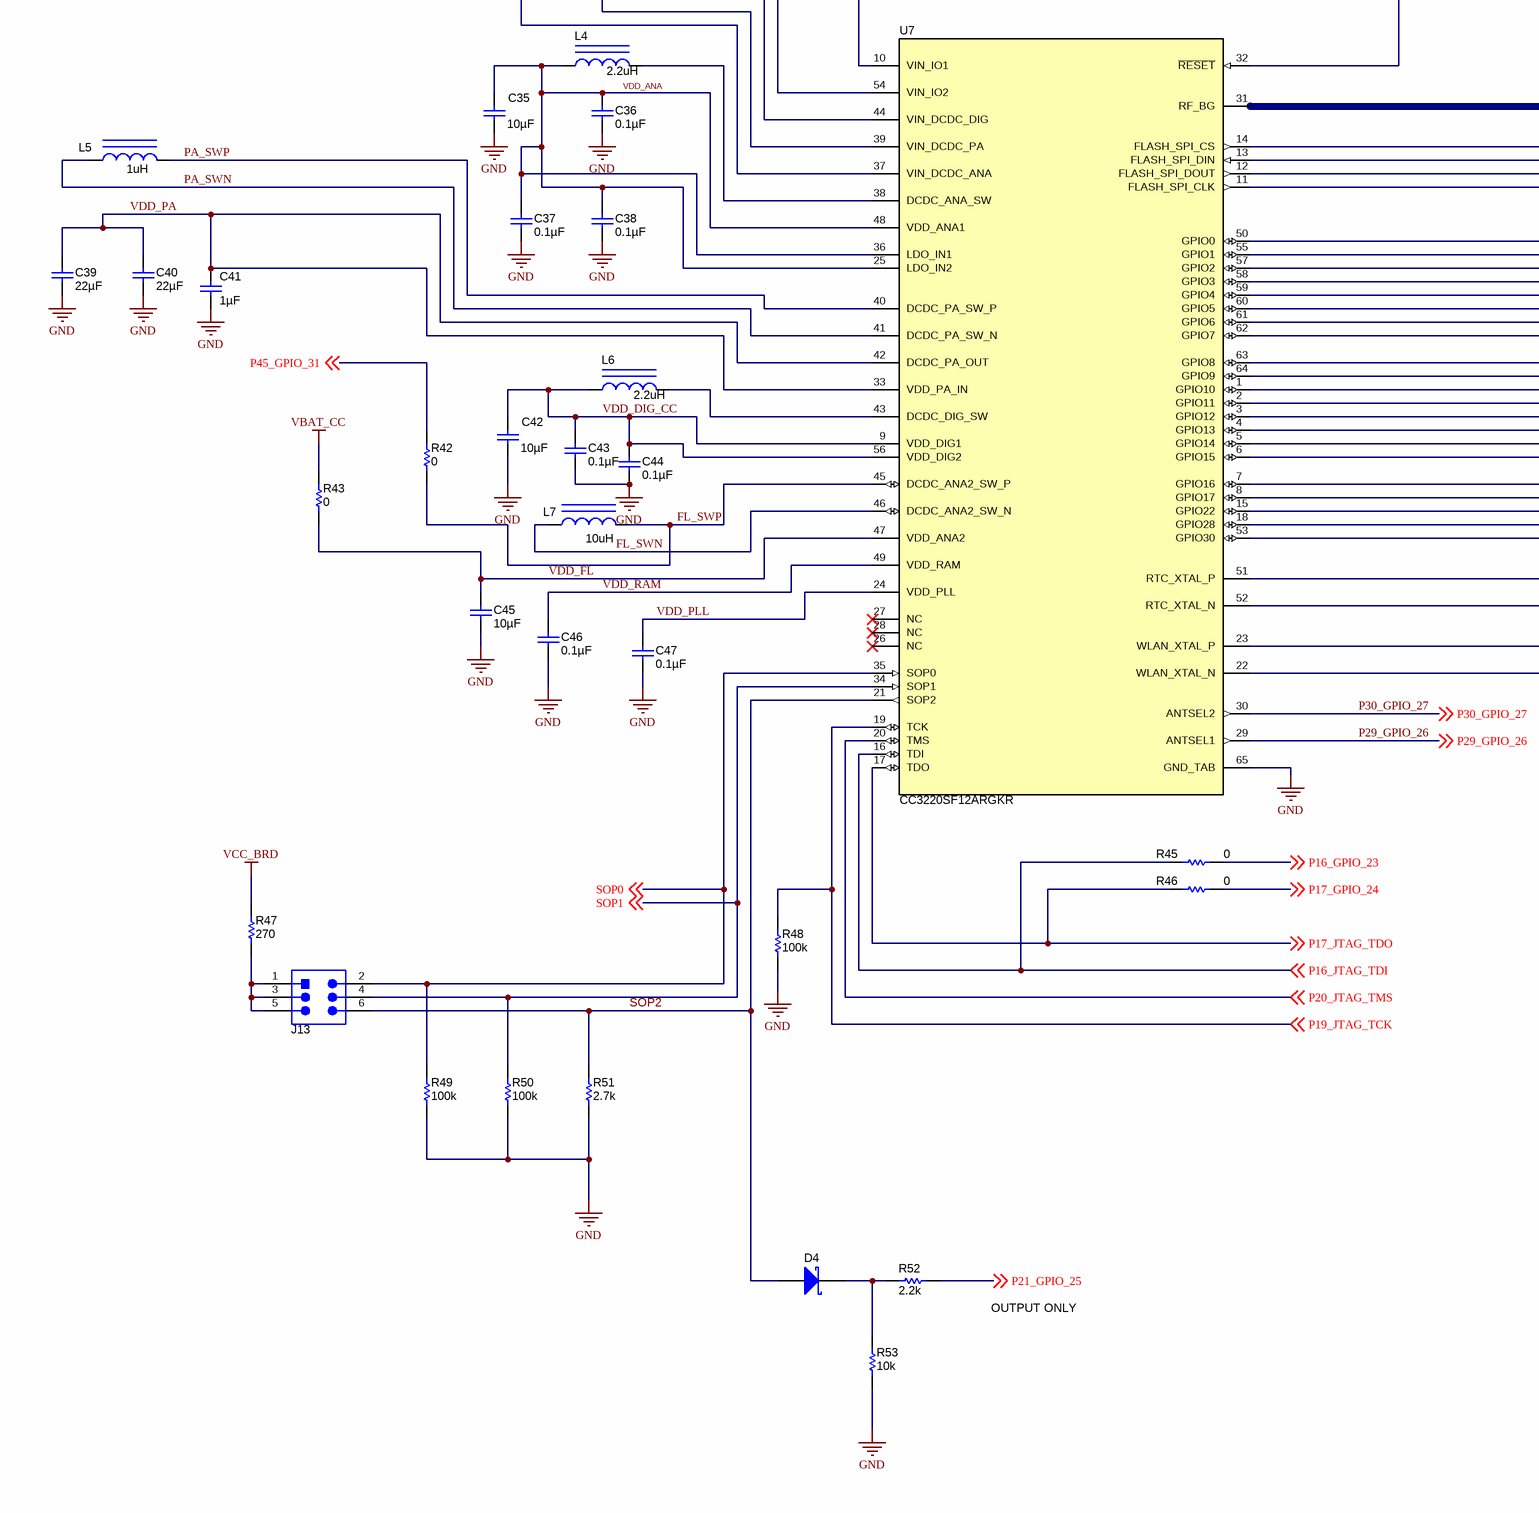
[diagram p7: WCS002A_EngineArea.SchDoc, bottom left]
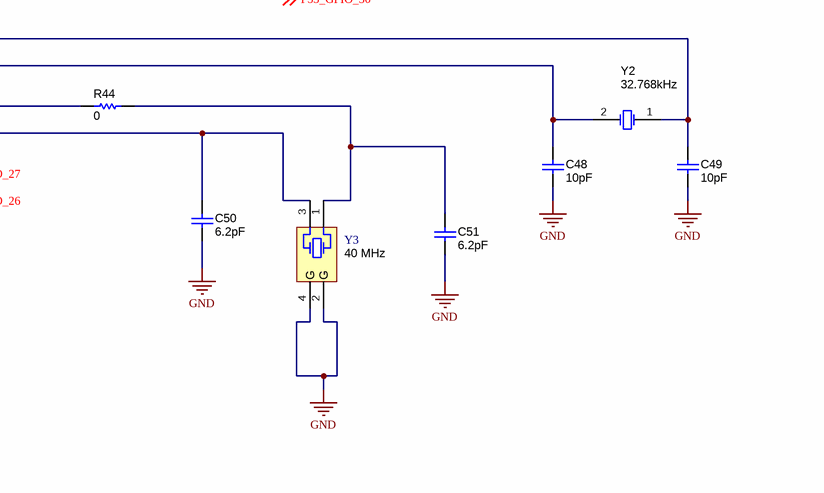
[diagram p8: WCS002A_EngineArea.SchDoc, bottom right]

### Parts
C26  ValueDisplayed: 10pF  [0402]  (hidden comment: GRM1555C1H100JA01D)
C27  ValueDisplayed: 1µF  [0402]  (hidden comment: GRM155R61A105KE15D)
C28  ValueDisplayed: 0.1µF  [0402]  (hidden comment: C1005X5R1A104K050BA)
C29  ValueDisplayed: 4.7µF  [0402]  (hidden comment: C1005X5R0J475M050BC)
C30  ValueDisplayed: 4.7µF  [0402]  (hidden comment: C1005X5R0J475M050BC)
C31  ValueDisplayed: 4.7µF  [0402]  (hidden comment: C1005X5R0J475M050BC)
C32  ValueDisplayed: 0.1µF  [0402]  (hidden comment: C1005X5R1A104K050BA)
C33  ValueDisplayed: 0.1µF  [0402]  (hidden comment: C1005X5R1A104K050BA)
C34  ValueDisplayed: 0.5pF  [0402]  (hidden comment: GJM1555C1HR50BB01J)
C35  ValueDisplayed: 10µF  [0603]  (hidden comment: GRM188R60J106ME47D)
C36  ValueDisplayed: 0.1µF  [0402]  (hidden comment: C1005X5R1A104K050BA)
C37  ValueDisplayed: 0.1µF  [0402]  (hidden comment: C1005X5R1A104K050BA)
C38  ValueDisplayed: 0.1µF  [0402]  (hidden comment: C1005X5R1A104K050BA)
C39  ValueDisplayed: 22µF  [0603]  (hidden comment: C1608X5R0G226M080AA)
C40  ValueDisplayed: 22µF  [0603]  (hidden comment: C1608X5R0G226M080AA)
C41  ValueDisplayed: 1µF  [0402]  (hidden comment: C1005X5R1A105K050BB)
C42  ValueDisplayed: 10µF  [0603]  (hidden comment: GRM188R60J106ME47D)
C43  ValueDisplayed: 0.1µF  [0402]  (hidden comment: C1005X5R1A104K050BA)
C44  ValueDisplayed: 0.1µF  [0402]  (hidden comment: C1005X5R1A104K050BA)
C45  ValueDisplayed: 10µF  [0603]  (hidden comment: GRM188R60J106ME47D)
C46  ValueDisplayed: 0.1µF  [0402]  (hidden comment: C1005X5R1A104K050BA)
C47  ValueDisplayed: 0.1µF  [0402]  (hidden comment: C1005X5R1A104K050BA)
C48  ValueDisplayed: 10pF  [0402]  (hidden comment: GRM1555C1H100JA01D)
C49  ValueDisplayed: 10pF  [0402]  (hidden comment: GRM1555C1H100JA01D)
C50  ValueDisplayed: 6.2pF  [0402]  (hidden comment: GRM1555C1H6R2CA01D)
C51  ValueDisplayed: 6.2pF  [0402]  (hidden comment: GRM1555C1H6R2CA01D)
D4  CD0603-B00340  [Diode_0603]  (value not drawn)
E1  AH316M245001-T  [TAYO_AH316M]  (value not drawn)
FL1  DEA202450BT-1294C1-H  [TDK_DEA202450BT-1294C1-H]  (value not drawn)
J9  61300211121  [WURTH_61300211121]  (value not drawn)
J10  U.FL-R-SMT-1  [CONN_UFL-R-SMT-1]  (value not drawn)
J11  MM8030-2610RJ3  [MuRata_MM8030-2610]  (value not drawn)
J12  TC2050-IDC-430-FP  [TC2050-IDC-430-FP]  (value not drawn)  (no BOM)
J13  61300621121  [Wurth_61300621121]  (value not drawn)
L3  value 3.3nH  [IND_LQG15H]  (hidden comment: LQG15HS3N3S02D)
L4  value 2.2uH  [1008]  (hidden comment: LQM2HPN2R2MG0L)
L5  value 1uH  [1008]  (hidden comment: LQM2HPN1R0MG0L)
L6  value 2.2uH  [1008]  (hidden comment: LQM2HPN2R2MG0L)
L7  value 10uH  [CBC2518]  (hidden comment: CBC2518T100M)
R35  ValueDisplayed: 10k  [0402]  (hidden comment: CRCW040210K0JNED)
R36  ValueDisplayed: 0  [0603]  (hidden comment: ERJ-3GEY0R00V)
R37  ValueDisplayed: 0  [0402]  (hidden comment: ERJ-2GE0R00X)
R38  ValueDisplayed: 0  [0402]  (hidden comment: ERJ-2GE0R00X)
R39  ValueDisplayed: 0  [0402]  (hidden comment: ERJ-2GE0R00X)
R40  ValueDisplayed: 0  [0402]  (hidden comment: ERJ-2GE0R00X)
R41  ValueDisplayed: 100k  [0402]  (hidden comment: CRCW0402100KJNED)
R42  ValueDisplayed: 0  [0402]  (hidden comment: ERJ-2GE0R00X)
R43  ValueDisplayed: 0  [0402]  (hidden comment: ERJ-2GE0R00X)
R44  ValueDisplayed: 0  [0402]  (hidden comment: ERJ-2GE0R00X)
R45  ValueDisplayed: 0  [0402]  (hidden comment: ERJ-2GE0R00X)
R46  ValueDisplayed: 0  [0402]  (hidden comment: ERJ-2GE0R00X)
R47  ValueDisplayed: 270  [0402]  (hidden comment: CRCW0402270RJNED)
R48  ValueDisplayed: 100k  [0402]  (hidden comment: CRCW0402100KJNED)
R49  ValueDisplayed: 100k  [0402]  (hidden comment: CRCW0402100KJNED)
R50  ValueDisplayed: 100k  [0402]  (hidden comment: CRCW0402100KJNED)
R51  ValueDisplayed: 2.7k  [0402]  (hidden comment: CRCW04022K70JNED)
R52  ValueDisplayed: 2.2k  [0402]  (hidden comment: CRCW04022K20JNED)
R53  ValueDisplayed: 10k  [0402]  (hidden comment: CRCW040210K0JNED)
U7  CC3220SF12ARGKR  [RGK0064B]
U8  MX25R3235FM1IL0  [SOP-8_150MIL]
Y2  Frequency: 32.768kHz  [XTAL_ABS07]  (hidden comment: ABS07-32.768KHZ-9-T)
Y3  Frequency: 40 MHz  [Epson_FA-20H]  (hidden comment: Q24FA20H0039600)

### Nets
GND: C27.2 C28.2 C29.2 C30.2 C31.2 C32.2 C33.2 C34.1 C34.2 C35.2 C36.2 C37.2 C38.2 C39.2 C40.2 C41.2 C42.2 C43.2 C44.2 C45.2 C46.2 C47.2 C48.2 C49.2 C50.2 C51.2 E1.1 E1.2 FL1.2(GND) FL1.4(GND) J10.2 J10.3 J11.3(GND) J11.4(GND) J12.1 J12.9 L3.2 R48.2 R49.2 R50.2 R51.2 R53.2 U7.65(GND_TAB) U8.4(GND) Y3.2(GND) Y3.4(GND)
VBAT_CC: C29.1 C30.1 C31.1 J9.2 R36.2 R39.2 R43.2 U7.37(VIN_DCDC_ANA) U7.39(VIN_DCDC_PA) U7.44(VIN_DCDC_DIG)
VCC_BRD: R38.2 R47.1
CC_nRESET: C27.1 J12.2 R35.2 U7.32(~{RESET}) ; off-sheet CC_nRESET
FL_SWN: L7.1 U7.46(DCDC_ANA2_SW_N)
FL_SWP: L7.2 R42.1 U7.45(DCDC_ANA2_SW_P)
P01_GPIO_10: U7.1(GPIO10) ; off-sheet P01_GPIO_10
P02_GPIO_11: U7.2(GPIO11) ; off-sheet P02_GPIO_11
P03_GPIO_12: U7.3(GPIO12) ; off-sheet P03_GPIO_12
P04_GPIO_13: U7.4(GPIO13) ; off-sheet P04_GPIO_13
P05_GPIO_14: U7.5(GPIO14) ; off-sheet P05_GPIO_14
P06_GPIO_15: U7.6(GPIO15) ; off-sheet P06_GPIO_15
P07_GPIO_16: U7.7(GPIO16) ; off-sheet P07_GPIO_16
P08_GPIO_17: U7.8(GPIO17) ; off-sheet P08_GPIO_17
P15_GPIO_22: U7.15(GPIO22) ; off-sheet P15_GPIO_22
P16_GPIO_23: R45.2 ; off-sheet P16_GPIO_23
P16_JTAG_TDI: R45.1 U7.16(TDI) ; off-sheet P16_JTAG_TDI
P17_GPIO_24: R46.2 ; off-sheet P17_GPIO_24
P17_JTAG_TDO: R46.1 U7.17(TDO) ; off-sheet P17_JTAG_TDO
P18_GPIO_28: U7.18(GPIO28) ; off-sheet P18_GPIO_28
P19_JTAG_TCK: R48.1 U7.19(TCK) ; off-sheet P19_JTAG_TCK
P20_JTAG_TMS: U7.20(TMS) ; off-sheet P20_JTAG_TMS
P21_GPIO_25: R52.2 ; off-sheet P21_GPIO_25
P29_GPIO_26: U7.29(ANTSEL1) ; off-sheet P29_GPIO_26
P30_GPIO_27: U7.30(ANTSEL2) ; off-sheet P30_GPIO_27
P45_GPIO_31: R42.2 ; off-sheet P45_GPIO_31
P50_GPIO_00: U7.50(GPIO0) ; off-sheet P50_GPIO_00
P53_GPIO_30: U7.53(GPIO30) ; off-sheet P53_GPIO_30
P55_GPIO_01: U7.55(GPIO1) ; off-sheet P55_GPIO_01
P57_GPIO_02: U7.57(GPIO2) ; off-sheet P57_GPIO_02
P58_GPIO_03: U7.58(GPIO3) ; off-sheet P58_GPIO_03
P59_GPIO_04: U7.59(GPIO4) ; off-sheet P59_GPIO_04
P60_GPIO_05: U7.60(GPIO5) ; off-sheet P60_GPIO_05
P61_GPIO_06: U7.61(GPIO6) ; off-sheet P61_GPIO_06
P62_GPIO_07: U7.62(GPIO7) ; off-sheet P62_GPIO_07
P63_GPIO_08: U7.63(GPIO8) ; off-sheet P63_GPIO_08
P64_GPIO_09: U7.64(GPIO9) ; off-sheet P64_GPIO_09
PA_SWN: L5.1 U7.41(DCDC_PA_SW_N)
PA_SWP: L5.2 U7.40(DCDC_PA_SW_P)
SFL_CLK: J12.8 U7.11(FLASH_SPI_CLK) U8.6(SCLK)
SFL_CS: J12.10 R41.2 U7.14(FLASH_SPI_CS) U8.1(~{CS})
SFL_DIN: J12.6 U7.13(FLASH_SPI_DIN) U8.2(SO/SIO1)
SFL_DOUT: J12.7 U7.12(FLASH_SPI_DOUT) U8.5(SI/SIO0)
SOP0: J13.2 R49.1 U7.35(SOP0) ; off-sheet SOP0
SOP1: J13.4 R50.1 U7.34(SOP1) ; off-sheet SOP1
SOP2: D4.2(A) J13.6 R51.1 U7.21(SOP2)
VDD_ANA: C35.1 C36.1 C37.1 C38.1 L4.1 U7.25(LDO_IN2) U7.36(LDO_IN1) U7.48(VDD_ANA1)
VDD_DIG_CC: C42.1 C43.1 C44.1 L6.1 U7.9(VDD_DIG1) U7.56(VDD_DIG2)
VDD_FL: C45.1 R43.1 U7.47(VDD_ANA2)
VDD_PA: C39.1 C40.1 C41.1 U7.33(VDD_PA_IN) U7.42(DCDC_PA_OUT)
VDD_PLL: C47.1 U7.24(VDD_PLL)
VDD_RAM: C46.1 U7.49(VDD_RAM)
NetC26_1: C26.1 R37.2
NetC26_2: C26.2 J10.1
NetC28_1: C28.1 C32.1 R36.1 U7.10(VIN_IO1) U7.54(VIN_IO2)
NetC33_1: C33.1 R38.1 R39.1 R41.1 U8.3(~{WP}/SIO2) U8.7(~{RESET}/SIO3) U8.8(VCC)
NetC48_1: C48.1 U7.52(RTC_XTAL_N) Y2.2(OSC2)
NetC49_1: C49.1 U7.51(RTC_XTAL_P) Y2.1(OSC1)
NetC50_1: C50.1 U7.22(WLAN_XTAL_N) Y3.3
NetC51_1: C51.1 R44.1 Y3.1
NetD4_1: D4.1(K) R52.1 R53.1
NetFL1_1: FL1.1(IN) U7.31(RF_BG)
NetFL1_3: FL1.3(OUT) R37.1 R40.1
NetJ9_1: J9.1 R35.1
NetJ11_1: J11.1(IN) R40.2
NetJ11_2: J11.2(OUT) L3.1
NetJ13_1: J13.1 J13.3 J13.5 R47.2
NetL4_2: L4.2 U7.38(DCDC_ANA_SW)
NetL6_2: L6.2 U7.43(DCDC_DIG_SW)
NetR44_2: R44.2 U7.23(WLAN_XTAL_P)

Not connected (* = marked no-connect by the designer): J12 3* 4* 5*; U7 26(NC)* 27(NC)* 28(NC)*

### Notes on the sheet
- (near E1) Feed
- OUTPUT ONLY

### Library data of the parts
C26 C48 C49 = GRM1555C1H100JA01D: CAP, CERM, 10 pF, 50 V, +/- 5%, C0G/NP0, 0402; Manufacturer: MuRata; Polarized: N; CompType: Capacitor; Value: 10pF; U/M: EA; Cap_F: 0.00000000001; Tolerance_%: 5; Value1: Unknown; VDC_V: 50; Value2: 50V; TaMin_C: -55; TaMax_C: 125
C27 = GRM155R61A105KE15D: CAP, CERM, 1 µF, 10 V, +/- 10%, X5R, 0402; Manufacturer: MuRata; Polarized: N; CompType: Capacitor; Value: 1uF; U/M: EA; Cap_F: 0.000001; Tolerance_%: 10; Value1: Unknown; Value2: 10V; TaMin_C: -55; TaMax_C: 85
C28 C32 C33 C36-C38 C43 C44 C46 C47 = C1005X5R1A104K050BA: as C1 on sheet WCS002A_EmulationCircuit
C29-C31 = C1005X5R0J475M050BC: CAP, CERM, 4.7 µF, 6.3 V, +/- 20%, X5R, 0402; Manufacturer: TDK; Polarized: N; CompType: Capacitor; Value: 4.7uF; U/M: EA; Cap_F: 0.0000047; Tolerance_%: 20; Value1: Unknown; VDC_V: 6.3; Value2: 6.3V; TaMin_C: -55; TaMax_C: 85
C34 = GRM1555C1H1R0BA01D: CAP, CERM, 0.5 pF, 50 V, +/- 10%, C0G/NP0, 0402; Manufacturer: MuRata; Polarized: N; CompType: Capacitor; Value: 0.5pF; U/M: EA; Cap_F: 0.000000000001; Tolerance_%: 10; Value1: Unknown; VDC_V: 50; Value2: 50V; TaMin_C: -55; TaMax_C: 125
C35 C42 C45 = GRM188R60J106ME47D: CAP, CERM, 10 µF, 6.3 V, +/- 20%, X5R, 0603; Manufacturer: MuRata; Polarized: N; CompType: Capacitor; Value: 10uF; U/M: EA; Cap_F: 0.00001; Tolerance_%: 20; ESR_ohm: 0.009; Value1: 0.009 ohm; VDC_V: 6.3; Value2: 6.3V; IRMS_A: 2.74; TaMin_C: -55; TaMax_C: 125
C39 C40 = C1608X5R0G226M080AA: CAP, CERM, 22 µF, 4 V, +/- 20%, X5R, 0603; Manufacturer: TDK; Polarized: N; CompType: Capacitor; Value: 22uF; U/M: EA; Cap_F: 0.000022; Tolerance_%: 20; Value1: Unknown; VDC_V: 4; Value2: 4V; TaMin_C: -55; TaMax_C: 85
C41 = C1005X5R1A105K050BB: CAP, CERM, 1 µF, 10 V, +/- 10%, X5R, 0402; Manufacturer: TDK; Polarized: N; CompType: Capacitor; Value: 1uF; U/M: EA; Cap_F: 0.000001; Tolerance_%: 10; Value1: Unknown; Value2: 10V; TaMin_C: -55; TaMax_C: 85
C50 C51 = GRM1555C1H6R2CA01D: CAP, CERM, 6.2 pF, 50 V, +/- 5%, C0G/NP0, 0402; Manufacturer: MuRata; Polarized: N; CompType: Capacitor; Value: 6.2pF; U/M: EA; Cap_F: 0.0000000000062; Tolerance_%: 5; Value1: Unknown; VDC_V: 50; Value2: 50V; TaMin_C: -55; TaMax_C: 125
D4 = CD0603-B00340: Diode, Schottky, 45 V, 0.03 A, 0603 Diode; Manufacturer: Bourns; U/M: EA; Vf_V: 0.37; Value: 45V; Value1: 0.03A; Value2: 0.37V; Io_A: 0.03; Vr_V: 45; TJmax_C: 125; AEC Category: Q101
E1 = AH316M245001-T: ANT BLUETOOTH W-LAN ZIGBEE WIMAX, SMD; Manufacturer: Taiyo Yuden; SymbolCreator: a0411947; CompType: Antenna
FL1 = DEA202450BT-1294C1-H: Multilayer Chip Band Pass Filter For 2.4GHz W-LAN/Bluetooth, SMD; Manufacturer: TDK; SymbolCreator: Altium; Value: 1.02 dB
J9 = 61300211121: Header, 2.54 mm, 2x1, Gold, TH; Manufacturer: Wurth Elektronik; SymbolCreator: a0412235; U/M: EA
J10 = U.FL-R-SMT-1: Connector, Ultra-Mini Coaxial, SMD; Manufacturer: Hirose Electric Co. Ltd.; SymbolCreator: a0412235; U/M: EA
J11 = MM8030-2610RJ3: Coaxial Connectors with Switch, 50 Ohm, SMD; Manufacturer: MuRata; SymbolCreator: Altium; U/M: EA
J12 = TC2050-IDC-430-FP: Footprint for TC2050-IDC-430; Manufacturer: Tag-Connect; SymbolCreator: a0799628; CompType: Receptacle; U/M: EA; Note: Footprint only, to mate with Tag-Connect cable P/N TC2050-IDC-430
J13 = 61300621121: Header, 2.54mm, 3x2, Gold, TH; Manufacturer: Wurth Elektronik; SymbolCreator: a0412235; U/M: EA
L3 = LQG15HS3N3S02D: Inductor, Multilayer, Air Core, 3.3 nH, 0.3 A, 0.17 ohm, SMD; Manufacturer: MuRata; Ind_H: 3.3E-9; Imax_A: 0.3; Irms: 0.3A @ C rise; Isat: 0.3A @ % inductance drop; DCR_ohm: 0.17; Value2: 0.3A
L4 L6 = LQM2HPN2R2MG0L: Inductor, Multilayer, Ferrite, 2.2 µH, 1.3 A, 0.08 ohm, SMD; Manufacturer: MuRata; Ind_H: 2.2E-6; ValueDisplayed: 2.2µH; Imax_A: 1.3; Irms: 1.3A @ 40C rise; DCR_ohm: 0.08; Value2: 1.3A
L5 = LQM2HPN1R0MG0L: Inductor, Multilayer, Ferrite, 1 µH, 1.6 A, 0.055 ohm, SMD; Manufacturer: MuRata; Ind_H: 1.0E-6; ValueDisplayed: 1µH; Imax_A: 1.6; Irms: 1.6A @ 40C rise; DCR_ohm: 0.055; Value2: 1.6A
L7 = CBC2518T100M: Inductor, Wirewound, Ceramic, 10 µH, 0.48 A, 0.36 ohm, SMD; Manufacturer: Taiyo Yuden; Ind_H: 10.0E-6; ValueDisplayed: 10µH; Imax_A: 0.48; Irms: 0.68A @ 40C rise; Isat: 0.48A @ 30% inductance drop; DCR_ohm: 0.36; Value2: 0.48A
R35 R53 = CRCW040210K0JNED: as R20 on sheet WCS002A_EmulationCircuit
R36 = ERJ-3GEY0R00V: RES, 0, 5%, 0.1 W, 0603; Manufacturer: Panasonic; CompType: Resistor; Value: 0; Value_Code: 0000; Tolerance_%: 5; Power_W: 0.1; Value2: 0.1W; VDC_V: 50; TempCo: 600 ppm/C; EIA_Code: E24; U/M: EA
R37 R40 R42-R45 = ERJ-2GE0R00X: as R12 on sheet WCS002A_EmulationCircuit
R38 R39 R46 = ERJ-2GE0R00X: RES, 0, 5%, 0.063 W, 0402; Manufacturer: Panasonic; CompType: Resistor; Value: 0; Value_Code: 0000; Tolerance_%: 5; Power_W: 0.063; Value2: 0.063W; VDC_V: 50; TempCo: 600 ppm/C; EIA_Code: E24; U/M: EA; AEC Category: Q200
R41 R48-R50 = CRCW0402100KJNED: as R17 on sheet WCS002A_EmulationCircuit
R47 = CRCW0402270RJNED: RES, 270, 5%, 0.063 W, 0402; Manufacturer: Vishay-Dale; CompType: Resistor; Value: 270; Value_Code: 270R; Tolerance_%: 5; Power_W: 0.063; Value2: 0.063W; VDC_V: 50; TempCo: 200 ppm/C; EIA_Code: E24; U/M: EA
R51 = CRCW04022K70JNED: RES, 2.7 k, 5%, 0.063 W, 0402; Manufacturer: Vishay-Dale; CompType: Resistor; Value: 2.7k; Res_ohm: 2700; Value_Code: 2k70; Tolerance_%: 5; Power_W: 0.063; Value2: 0.063W; VDC_V: 50; TempCo: 200 ppm/C; EIA_Code: E24; U/M: EA; SizeArea_mm2: 0.5; SizeX_mm: 1; SizeZ_mm: 0.6; AEC Category: Q200
R52 = CRCW04022K20JNED: RES, 2.2 k, 5%, 0.063 W, 0402; Manufacturer: Vishay-Dale; CompType: Resistor; Value: 2.2k; Res_ohm: 2200; Value_Code: 2k20; Tolerance_%: 5; Power_W: 0.063; Value2: 0.063W; VDC_V: 50; TempCo: 200 ppm/C; EIA_Code: E24; U/M: EA; AEC Category: Q200
U7 = CC3220SF12ARGKR: SimpleLink Wi-Fi and Internet-of-Things Solution, a Single-Chip Wireless MCU, RGK0064B (VQFN-64); Alternate PartNumber: CC3220SF12ARGKT; Manufacturer: Texas Instruments; SymbolCreator: Altium; CompType: IC; U/M: EA; SizeArea_mm2: 81; SizeAreaWB_mm2: 121; SizeX_mm: 9; SizeZ_mm: 1
U8 = MX25R3235FM1IL0: ULTRA LOW POWER, 32M-BIT [x 1/x 2/x 4] CMOS MXSMIO(SERIAL MULTI I/O) FLASH MEMORY, SOP-8; Manufacturer: Macronix International Co., LTD; SymbolCreator: Altium
Y2 = ABS07-32.768KHZ-9-T: CRYSTAL, 32.768KHZ, 9PF, SMD; Manufacturer: Abracon Corportation; SymbolCreator: a0412235; U/M: EA; TaMin_C: -40; TaMax_C: 85; Frequency Stability: ±20ppm
Y3 = Q24FA20H0039600: Crystal, 40MHz, 8pF, SMD; Manufacturer: Epson; SymbolCreator: a0412235; U/M: EA; TaMin_C: -30; TaMax_C: 85; Frequency Stability: ±7ppm

## Sheet WCS002A_EVM_Hardware.SchDoc: EVM Hardware
size 558 x 431 mm; Date: Not shown in title block; ApprovedBy: Not shown in title block; CheckedBy: Not shown in title block; Author: Not shown in title block; CompanyName: Not shown in title block; Engineer: Not shown in title block; Organization: Not shown in title block; Address1: Not shown in title block; Address2: Not shown in title block; Address3: Not shown in title block; Address4: Not shown in title block; DocumentNumber: 6; Revision: Use project parameter SCH_Rev; SheetNumber: 6; SheetTotal: 6; PageSetup: Record=PageOptions¦CenterHorizontal=True¦CenterVertical=True¦PrintScale=1.00¦XCorrection=1.00¦YCorrection=1.00¦PrintKind=0¦BorderSize=5000000¦LeftOffset=0¦BottomOffset=0¦Orientation=2¦PaperLength=1000¦PaperWidth=1000¦Scale=100¦PaperSource=15¦PrintQuality=600¦MediaType=1¦DitherType=10¦PaperKind=Letter¦PrintScaleMode=1
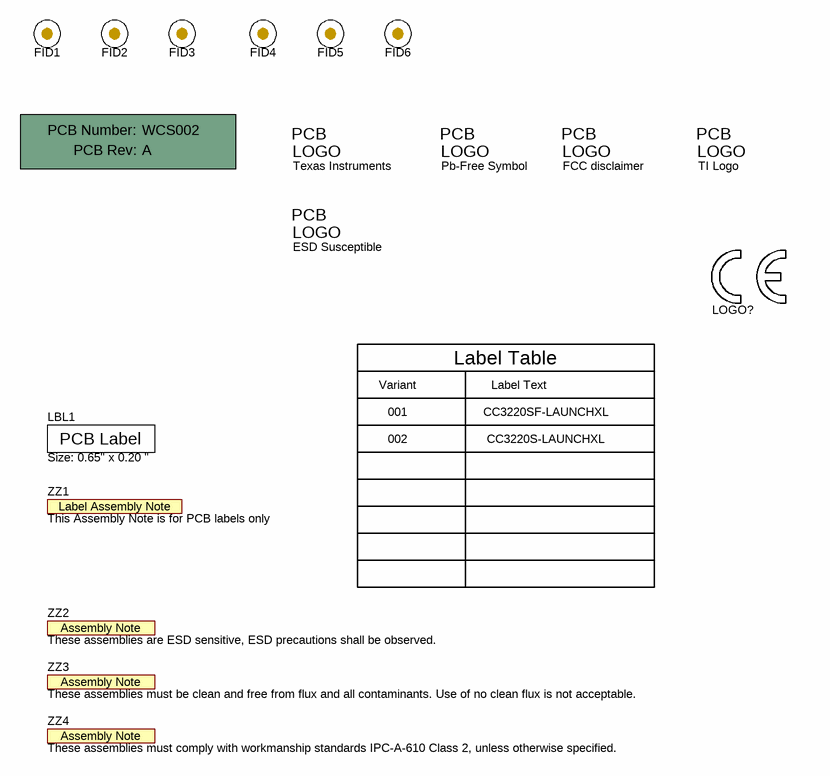
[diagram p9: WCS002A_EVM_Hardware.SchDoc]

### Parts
!PCB1  Printed Circuit Board  (value not drawn)  (mechanical)
FID1  Fiducial  [Fiducial10-20]  (value not drawn)
FID2  Fiducial  [Fiducial10-20]  (value not drawn)
FID3  Fiducial  [Fiducial10-20]  (value not drawn)
FID4  Fiducial  [Fiducial10-20]  (value not drawn)
FID5  Fiducial  [Fiducial10-20]  (value not drawn)
FID6  Fiducial  [Fiducial10-20]  (value not drawn)
LBL1  Size: 0.65" x 0.20 "  [Label_650x200]
Logo1  Texas Instruments  [TI_Stacked_Overlay_Small]  (no BOM)
Logo2  Pb-Free Symbol  [Pb-Free_Overlay_Medium]  (no BOM)
Logo3  FCC disclaimer  [FCC_disclaimer]  (no BOM)
Logo4  ESD Susceptible  [ESD_Overlay_Medium]  (no BOM)
LOGO?  CE Mark  [CE_Mark_5mm]  (value not drawn)  (no BOM)
TI_Logo  Texas Instruments  [TI_Symbol_Overlay_Small]  (value not drawn)  (no BOM)
ZZ1  This Assembly Note is for PCB labels only  [AssemblyNoteLabel]  (no BOM)
ZZ2  These assemblies are ESD sensitive, ESD precautions shall be observed.  [AssemblyNote]  (no BOM)
ZZ3  These assemblies must be clean and free from flux and all contaminants. Use of no clean flux is not acceptable.  [AssemblyNote]  (no BOM)
ZZ4  These assemblies must comply with workmanship standards IPC-A-610 Class 2, unless otherwise specified.  [AssemblyNote]  (no BOM)

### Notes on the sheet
- Variant
- Label Table
- Label Text
- 001
- 002
- CC3220SF-LAUNCHXL
- CC3220S-LAUNCHXL

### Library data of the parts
!PCB1 = PCB: Manufacturer: Any; PartNumber: WCS002; SymbolCreator: a0412235
FID1-FID6 = Fiducial: Fiducial mark.  There is nothing to buy or mount.; SymbolCreator: codlsc
LBL1 = THT-14-423-10: Thermal Transfer Printable Labels, 0.650" W x 0.200" H - 10,000 per roll; Manufacturer: Brady; SymbolCreator: a0412235; CompType: Label
Logo1 = TI_Logo: Texas Instrument Corporate Signature; SymbolCreator: codlsc
Logo2 = Pb-Free: SymbolCreator: a0412235
Logo3 = FCC_disclaimer: SymbolCreator: codlsc
Logo4 = ESD_Susceptible: ESD Susceptible Symbol; SymbolCreator: a0412235
LOGO? = CE Mark: SymbolCreator: a0412235
TI_Logo = TI_Logo: Texas Instrument Corporate Signature; SymbolCreator: a0412235
ZZ1 = AssemblyNoteLabel: SymbolCreator: a0412235
ZZ2-ZZ4 = AssemblyNote: SymbolCreator: codlsc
